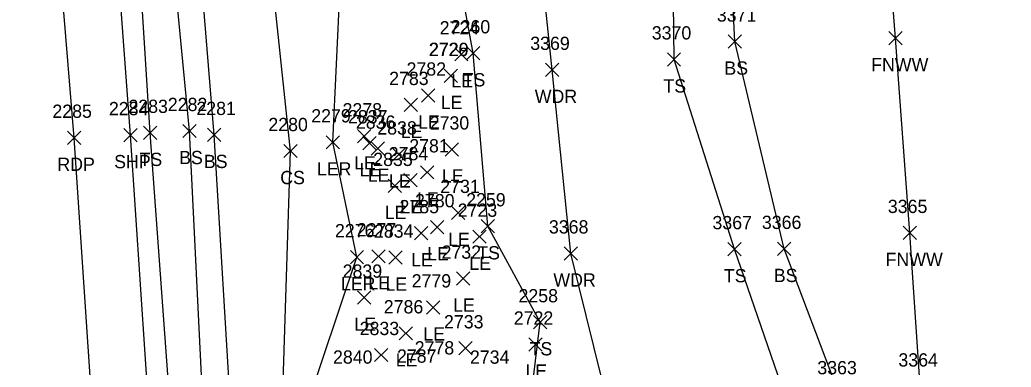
# Model space of a CAD drawing. Extents: x 1650221 to 1650634, y 244606 to 249996.
# Drawn here: x 1650353.8 to 1650503.1, y 246425.2 to 246477.6 of the extents above; entities that cross this region are included whole.
import ezdxf

# ---------------------------------------------------------------- set-up
doc = ezdxf.new("R2010")
doc.units = 0
for name, color, linetype in [('L_A', 7, 'Continuous'), ('L_I', 7, 'Continuous'), ('L_TIC', 7, 'Continuous'), ('LARO', 7, 'Continuous'), ('LAWA', 7, 'Continuous'), ('LELB', 7, 'Continuous'), ('LFNC', 7, 'Continuous'), ('LSOGP', 7, 'Continuous'), ('P_A', 7, 'Continuous'), ('P_I', 7, 'Continuous'), ('P_TIC', 7, 'Continuous'), ('PET', 7, 'Continuous'), ('PSP', 7, 'Continuous')]:
    doc.layers.add(name, color=color, linetype=linetype)

msp = doc.modelspace()

# ---------------------------------------------------------------- linework, layer by layer
at = {"layer": 'L_TIC'}
for points in [[(1650460.43, 246473.29), (1650462.43, 246475.29)], [(1650462.43, 246473.29), (1650460.43, 246475.29)], [(1650484.64, 246473.81), (1650486.64, 246475.81)], [(1650486.64, 246473.81), (1650484.64, 246475.81)], [(1650419.26, 246471.36), (1650421.26, 246473.36)], [(1650421.26, 246471.36), (1650419.26, 246473.36)], [(1650421.05, 246471.52), (1650423.05, 246473.52)], [(1650423.05, 246471.52), (1650421.05, 246473.52)], [(1650451.29, 246470.6), (1650453.29, 246472.6)], [(1650453.29, 246470.6), (1650451.29, 246472.6)], [(1650432.96, 246469.02), (1650434.96, 246471.02)], [(1650434.96, 246469.02), (1650432.96, 246471.02)], [(1650417.67, 246468.11), (1650419.67, 246470.11)], [(1650419.67, 246468.11), (1650417.67, 246470.11)], [(1650417.67, 246468.1), (1650419.67, 246470.1)], [(1650419.67, 246468.1), (1650417.67, 246470.1)], [(1650414.27, 246465.15), (1650416.27, 246467.15)], [(1650416.27, 246465.15), (1650414.27, 246467.15)], [(1650411.65, 246463.73), (1650413.65, 246465.73)], [(1650413.65, 246463.73), (1650411.65, 246465.73)], [(1650378.32, 246459.8), (1650380.32, 246461.8)], [(1650380.32, 246459.8), (1650378.32, 246461.8)], [(1650372.39, 246459.52), (1650374.39, 246461.52)], [(1650374.39, 246459.52), (1650372.39, 246461.52)], [(1650382.05, 246459.21), (1650384.05, 246461.21)], [(1650384.05, 246459.21), (1650382.05, 246461.21)], [(1650404.63, 246459), (1650406.63, 246461)], [(1650406.63, 246459), (1650404.63, 246461)], [(1650399.93, 246458.09), (1650401.93, 246460.09)], [(1650401.93, 246458.09), (1650399.93, 246460.09)], [(1650405.45, 246457.95), (1650407.45, 246459.95)], [(1650407.45, 246457.95), (1650405.45, 246459.95)], [(1650406.69, 246457.14), (1650408.69, 246459.14)], [(1650408.69, 246457.14), (1650406.69, 246459.14)], [(1650417.84, 246457.02), (1650419.84, 246459.02)], [(1650419.84, 246457.02), (1650417.84, 246459.02)], [(1650393.55, 246456.78), (1650395.55, 246458.78)], [(1650395.55, 246456.78), (1650393.55, 246458.78)], [(1650409.87, 246456.26), (1650411.87, 246458.26)], [(1650411.87, 246456.26), (1650409.87, 246458.26)], [(1650411.59, 246452.38), (1650413.59, 246454.38)], [(1650413.59, 246452.38), (1650411.59, 246454.38)], [(1650414.12, 246453.57), (1650416.12, 246455.57)], [(1650416.12, 246453.57), (1650414.12, 246455.57)], [(1650409.25, 246451.52), (1650411.25, 246453.52)], [(1650411.25, 246451.52), (1650409.25, 246453.52)], [(1650418.78, 246447.45), (1650420.78, 246449.45)], [(1650420.78, 246447.45), (1650418.78, 246449.45)], [(1650415.63, 246445.29), (1650417.63, 246447.29)], [(1650417.63, 246445.29), (1650415.63, 246447.29)], [(1650423.25, 246445.43), (1650425.25, 246447.43)], [(1650425.25, 246445.43), (1650423.25, 246447.43)], [(1650413.21, 246444.39), (1650415.21, 246446.39)], [(1650415.21, 246444.39), (1650413.21, 246446.39)], [(1650421.98, 246443.86), (1650423.98, 246445.86)], [(1650423.98, 246443.86), (1650421.98, 246445.86)], [(1650486.8, 246444.43), (1650488.8, 246446.43)], [(1650488.8, 246444.43), (1650486.8, 246446.43)], [(1650460.39, 246441.98), (1650462.39, 246443.98)], [(1650462.39, 246441.98), (1650460.39, 246443.98)], [(1650467.88, 246442.02), (1650469.88, 246444.02)], [(1650469.88, 246442.02), (1650467.88, 246444.02)], [(1650403.55, 246440.77), (1650405.55, 246442.77)], [(1650405.55, 246440.77), (1650403.55, 246442.77)], [(1650406.77, 246440.9), (1650408.77, 246442.9)], [(1650408.77, 246440.9), (1650406.77, 246442.9)], [(1650409.36, 246440.71), (1650411.36, 246442.71)], [(1650411.36, 246440.71), (1650409.36, 246442.71)], [(1650435.75, 246441.34), (1650437.75, 246443.34)], [(1650437.75, 246441.34), (1650435.75, 246443.34)], [(1650419.54, 246437.54), (1650421.54, 246439.54)], [(1650421.54, 246437.54), (1650419.54, 246439.54)], [(1650404.65, 246434.67), (1650406.65, 246436.67)], [(1650406.65, 246434.67), (1650404.65, 246436.67)], [(1650415.04, 246433.2), (1650417.04, 246435.2)], [(1650417.04, 246433.2), (1650415.04, 246435.2)], [(1650431.13, 246430.96), (1650433.13, 246432.96)], [(1650433.13, 246430.96), (1650431.13, 246432.96)], [(1650410.9, 246429.29), (1650412.9, 246431.29)], [(1650412.9, 246429.29), (1650410.9, 246431.29)], [(1650419.91, 246427.03), (1650421.91, 246429.03)], [(1650421.91, 246427.03), (1650419.91, 246429.03)], [(1650430.42, 246427.6), (1650432.42, 246429.6)], [(1650432.42, 246427.6), (1650430.42, 246429.6)], [(1650407.2, 246426.02), (1650409.2, 246428.02)], [(1650409.2, 246426.02), (1650407.2, 246428.02)]]:
    msp.add_lwpolyline(points, dxfattribs=at)
at = {"layer": 'LARO'}
msp.add_lwpolyline([(1650408.62, 246217.57), (1650415.02, 246258.55), (1650416.03, 246285.89), (1650409.42, 246296.82), (1650403.38, 246341.57), (1650407.27, 246374.55), (1650399.81, 246378.86), (1650397.58, 246413.38), (1650396.61, 246418.12), (1650404.55, 246441.77), (1650400.93, 246459.09), (1650402.01, 246482.67), (1650393.67, 246489.39), (1650391.87, 246506.08), (1650398.3, 246543.79), (1650391.28, 246548.76), (1650385.03, 246598.74), (1650385.05, 246648.92)], dxfattribs=at)
at = {"layer": 'LAWA'}
msp.add_lwpolyline([(1650467.45, 246241.25), (1650457.44, 246253.74), (1650465.18, 246273.59), (1650462.12, 246310.22), (1650448.31, 246306.9), (1650448.47, 246334.54), (1650451.18, 246360.81), (1650449.4, 246391.83), (1650443.67, 246414.29), (1650436.75, 246442.34), (1650433.96, 246470.02), (1650430.34, 246504.78), (1650427.12, 246530.84), (1650425.66, 246560.12), (1650421.39, 246581.34), (1650411.43, 246590.25), (1650407.77, 246596.47), (1650408.99, 246611.27), (1650406.47, 246635.27)], dxfattribs=at)
at = {"layer": 'LELB'}
for points in [[(1650393.27, 246215.06), (1650388.59, 246258.03), (1650385.3, 246297.22), (1650382.89, 246338.27), (1650379.78, 246382.54), (1650376.7, 246415.11), (1650373.39, 246460.52), (1650370.35, 246509.11), (1650367.73, 246551.79), (1650362.79, 246601.35), (1650360.91, 246643.93), (1650360.73, 246683.45), (1650355.99, 246728.59), (1650353.01, 246770.02), (1650352.21, 246793.58), (1650347.7, 246827.18)], [(1650406.66, 246218.25), (1650409.74, 246258.01), (1650404.96, 246296.74), (1650400.85, 246340.5), (1650395.59, 246379.71), (1650393.17, 246415.1), (1650394.55, 246457.78), (1650389.36, 246506.84), (1650386.12, 246550.61), (1650380.92, 246598.97), (1650378.98, 246645.95), (1650376.23, 246684.96), (1650377.19, 246729.69), (1650373.96, 246768.95), (1650374.9, 246794.97)], [(1650398.42, 246215.35), (1650393.5, 246258.25), (1650390.33, 246297.07), (1650387.57, 246339.17), (1650383.09, 246382.59), (1650381.54, 246415.75), (1650379.32, 246460.8), (1650374.72, 246508.95), (1650372.6, 246551.63), (1650368.85, 246601.31), (1650366.31, 246644.43), (1650364.47, 246684.58), (1650363.63, 246728.26), (1650358.66, 246769.4), (1650355.43, 246788.13), (1650360.4, 246788.44)], [(1650402.25, 246216.69), (1650398.47, 246258.76), (1650395.79, 246297.15), (1650391.97, 246340.1), (1650387.54, 246382.07), (1650385.71, 246415.98), (1650383.05, 246460.21), (1650379.09, 246508.87), (1650375.79, 246552.14), (1650373.14, 246601), (1650370.95, 246644.96), (1650368.35, 246684.96), (1650368, 246727.84), (1650362.74, 246769.21), (1650360.4, 246788.44)], [(1650479.19, 246312.48), (1650486.78, 246343.04), (1650484.86, 246368.89), (1650480.94, 246392.32), (1650477.18, 246421.11), (1650468.88, 246443.02), (1650461.43, 246474.29), (1650459.99, 246504.26), (1650455.48, 246533.7), (1650468.39, 246557.95), (1650462.64, 246596.83), (1650458.65, 246616.06), (1650445.95, 246610.52), (1650432.73, 246599.27), (1650420.88, 246596.79), (1650423.87, 246613.47), (1650428.27, 246642.15), (1650440.67, 246654.81), (1650470.88, 246672.08), (1650450.6, 246689.53), (1650437.54, 246708.06), (1650451.69, 246713.27), (1650467.72, 246712.4)], [(1650445.18, 246217.4), (1650445.53, 246269.3), (1650441.9, 246297.75), (1650443.52, 246304.66), (1650437.79, 246334.62), (1650435.28, 246374.91), (1650430.35, 246417), (1650432.13, 246431.96), (1650424.25, 246446.43), (1650422.05, 246472.52), (1650416.53, 246502.71), (1650417.53, 246540.78), (1650409.48, 246565.5), (1650407.87, 246589.87), (1650402.92, 246599.27), (1650397.78, 246634.8)], [(1650479.19, 246312.48), (1650478.72, 246341.58), (1650480.51, 246366.06), (1650476.32, 246392.29), (1650469.92, 246418.18), (1650461.39, 246442.98), (1650452.29, 246471.6), (1650451.91, 246505.83), (1650450.21, 246533.17), (1650459.89, 246559.37), (1650456.99, 246596.58), (1650458.65, 246616.06)]]:
    msp.add_lwpolyline(points, dxfattribs=at)
at = {"layer": 'LFNC'}
msp.add_lwpolyline([(1650503.06, 246228.04), (1650500.95, 246260.24), (1650499.52, 246280.97), (1650496.75, 246319.42), (1650494.71, 246343.47), (1650493.4, 246369.97), (1650491.44, 246391.35), (1650489.38, 246422.28), (1650487.8, 246445.43), (1650485.64, 246474.81), (1650483.6, 246501.15), (1650481.03, 246533.54), (1650479.37, 246558.3), (1650476.37, 246602.1), (1650473.83, 246635.82)], dxfattribs=at)
at = {"layer": 'LSOGP'}
msp.add_lwpolyline([(1650503.06, 246228.04), (1650500.95, 246260.24), (1650499.52, 246280.97), (1650496.75, 246319.42), (1650494.71, 246343.47), (1650493.4, 246369.97), (1650491.44, 246391.35), (1650489.38, 246422.28), (1650487.8, 246445.43), (1650485.64, 246474.81), (1650483.6, 246501.15), (1650481.03, 246533.54), (1650479.37, 246558.3), (1650476.37, 246602.1), (1650473.83, 246635.82)], dxfattribs=at)
at = {"layer": 'P_TIC'}
for points in [[(1650360.94, 246458.78), (1650362.94, 246460.78)], [(1650362.94, 246458.78), (1650360.94, 246460.78)], [(1650369.45, 246459.18), (1650371.45, 246461.18)], [(1650371.45, 246459.18), (1650369.45, 246461.18)]]:
    msp.add_lwpolyline(points, dxfattribs=at)
at = {"layer": 'PET'}
msp.add_lwpolyline([(1650378.63, 246214.91), (1650375.8, 246256.56), (1650373.01, 246296.44), (1650370.08, 246336.2), (1650366.98, 246382.9), (1650364.95, 246414.8), (1650361.94, 246459.78), (1650357.93, 246508.74), (1650354.58, 246551.74), (1650350.86, 246600.91), (1650347.48, 246643.7), (1650346.09, 246667.41)], dxfattribs=at)
at = {"layer": 'PSP'}
msp.add_lwpolyline([(1650388.25, 246215.07), (1650385.02, 246257.59), (1650382.12, 246297.01), (1650379.04, 246337.67), (1650376.28, 246382.91), (1650373.45, 246415.13), (1650370.45, 246460.18), (1650366.83, 246508.93), (1650363.56, 246551.91), (1650360.5, 246601.39), (1650356.68, 246643.63), (1650355.13, 246668.21)], dxfattribs=at)

# ---------------------------------------------------------------- texts
at = {"layer": 'L_A'}
for s, p in [('BS', (1650459.87, 246469.29)), ('FNWW', (1650481.98, 246469.81)), ('LE', (1650418.75, 246467.36)), ('TS', (1650420.46, 246467.52)), ('TS', (1650450.69, 246466.6)), ('WDR', (1650431.32, 246465.02)), ('LE', (1650417.16, 246464.11)), ('LE', (1650417.16, 246464.1)), ('LE', (1650413.76, 246461.15)), ('LE', (1650411.14, 246459.73)), ('TS', (1650371.8, 246455.52)), ('BS', (1650377.77, 246455.8)), ('BS', (1650381.49, 246455.21)), ('LER', (1650398.51, 246454.09)), ('LE', (1650404.12, 246455)), ('LE', (1650404.94, 246453.95)), ('CS', (1650392.99, 246452.78)), ('LE', (1650406.18, 246453.14)), ('LE', (1650417.33, 246453.02)), ('LE', (1650409.36, 246452.26)), ('LE', (1650413.6, 246449.57)), ('LE', (1650411.08, 246448.38)), ('LE', (1650408.74, 246447.52)), ('LE', (1650418.27, 246443.45)), ('LE', (1650412.7, 246440.39)), ('LE', (1650415.12, 246441.29)), ('TS', (1650422.66, 246441.43)), ('FNWW', (1650484.15, 246440.43)), ('LE', (1650421.47, 246439.86)), ('TS', (1650459.8, 246437.98)), ('BS', (1650467.32, 246438.02)), ('LER', (1650402.13, 246436.77)), ('LE', (1650406.26, 246436.9)), ('LE', (1650408.84, 246436.71)), ('WDR', (1650434.12, 246437.34)), ('LE', (1650419.03, 246433.54)), ('LE', (1650404.14, 246430.67)), ('LE', (1650414.53, 246429.2)), ('TS', (1650430.54, 246426.96)), ('LE', (1650410.38, 246425.29)), ('LE', (1650429.91, 246423.6))]:
    msp.add_text(s, height=2, dxfattribs=at).set_placement(p)
at = {"layer": 'L_I'}
for s, p in [('3371', (1650458.74, 246477.29)), ('2724', (1650417, 246475.36)), ('2260', (1650418.66, 246475.52)), ('3370', (1650448.94, 246474.6)), ('2726', (1650415.35, 246472.1)), ('2729', (1650415.41, 246472.11)), ('3369', (1650430.64, 246473.02)), ('2782', (1650412.01, 246469.15)), ('2783', (1650409.39, 246467.73)), ('2283', (1650370.13, 246463.52)), ('2282', (1650376.06, 246463.8)), ('2281', (1650380.36, 246463.21)), ('2278', (1650402.37, 246463)), ('2279', (1650397.66, 246462.09)), ('2837', (1650403.19, 246461.95)), ('2280', (1650391.2, 246460.78)), ('2836', (1650404.38, 246461.14)), ('2838', (1650407.61, 246460.26)), ('2730', (1650415.5, 246461.02)), ('2781', (1650412.42, 246457.57)), ('2835', (1650406.99, 246455.52)), ('2784', (1650409.33, 246456.38)), ('2731', (1650417.09, 246451.45)), ('2259', (1650420.99, 246449.43)), ('2785', (1650410.95, 246448.39)), ('2780', (1650413.29, 246449.29)), ('2723', (1650419.72, 246447.86)), ('3365', (1650484.49, 246448.43)), ('2277', (1650404.51, 246444.9)), ('3368', (1650433.45, 246445.34)), ('3367', (1650458.08, 246445.98)), ('3366', (1650465.52, 246446.02)), ('2276', (1650401.23, 246444.77)), ('2834', (1650407.1, 246444.71)), ('2732', (1650417.28, 246441.54)), ('2839', (1650402.39, 246438.67)), ('2779', (1650412.78, 246437.2)), ('2258', (1650428.87, 246434.96)), ('2786', (1650408.58, 246433.29)), ('2722', (1650428.16, 246431.6)), ('2833', (1650404.95, 246430.02)), ('2733', (1650417.65, 246431.03)), ('2778', (1650413.24, 246427.1)), ('2840', (1650400.94, 246425.71)), ('2787', (1650410.57, 246425.86)), ('2734', (1650421.56, 246425.7)), ('3363', (1650473.87, 246424.11)), ('3364', (1650486.08, 246425.28))]:
    msp.add_text(s, height=2, dxfattribs=at).set_placement(p)
at = {"layer": 'P_A'}
for s, p in [('RDP', (1650359.43, 246454.78)), ('SHP', (1650367.98, 246455.18))]:
    msp.add_text(s, height=2, dxfattribs=at).set_placement(p)
at = {"layer": 'P_I'}
for s, p in [('2285', (1650358.68, 246462.78)), ('2284', (1650367.19, 246463.18))]:
    msp.add_text(s, height=2, dxfattribs=at).set_placement(p)

doc.saveas('drawing.dxf')
